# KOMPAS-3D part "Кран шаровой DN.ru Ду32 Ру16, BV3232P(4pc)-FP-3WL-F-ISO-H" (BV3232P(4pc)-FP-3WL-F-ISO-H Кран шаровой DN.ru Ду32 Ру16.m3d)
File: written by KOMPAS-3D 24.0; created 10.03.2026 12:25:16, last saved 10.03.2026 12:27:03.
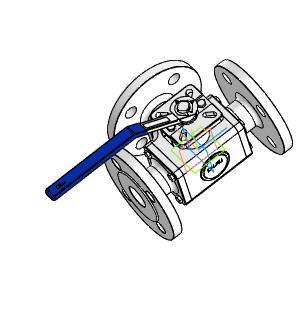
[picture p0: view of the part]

Document properties: Автор: R2D2; Полное имя файла: BV3232P(4pc)-FP-3WL-F-ISO-H Кран шаровой DN.ru Ду32 Ру16.cdw

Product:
- Part/product: Кран шаровой DN.ru Ду32 Ру16  | designation BV3232P(4pc)-FP-3WL-F-ISO-H
    Масса: 9.3
    Раздел спецификации: Прочие изделия
    Форматы листов документа: A3
    Примечание: D160-36358

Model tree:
1. Операция без истории:1

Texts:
  BV3232P(4pc)-FP-3WL-F-ISO-H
